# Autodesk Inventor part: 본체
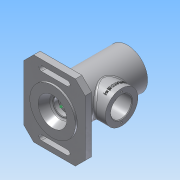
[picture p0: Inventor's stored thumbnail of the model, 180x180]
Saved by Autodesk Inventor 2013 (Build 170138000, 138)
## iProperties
Created: 2017-10
Part Number: 본체
Material: 알루미늄 6061
Document SubType Name: Modeling
Designer: Administrator
Density: 2.71 g/cm^3
Mass: 840.307 g
Surface Area: 700.57 cm^2
Volume: 310.076 cm^3
Author: Administrator
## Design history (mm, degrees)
sketch "스케치1"
  geometry: C1 r 31 at (0, 0); 1 further point
  constraints: 1 centre point, 1 coincident
  dimensions: "d0" = 62 diameter of C1
extrude "돌출1" new body sketch "스케치1" distance "d1" = 102; taper "d2" = 0 deg
node "작업 평면1"
sketch "스케치2"
  geometry: L1 (102, -31)-(102, 31) reference; C1 r 25 at (46, 0); 1 further point
  constraints: 1 centre point, 1 horizontal alignment
  dimensions: "d4" = 50 diameter of C1; "d5" = 56 distance from line of L1 C1.centre
extrude "돌출2" join sketch "스케치2" stored distance "d6" = 102; taper "d7" = 0 deg
sketch "스케치4"
  geometry: L1 (47, 58)-(-47, 58); L2 (-47, 58)-(-47, -58); L3 (-47, -58)-(47, -58); L4 (47, -58)-(47, 58); C1 r 31 at (0, 0) reference; 1 further point
  constraints: 8 end point, 2 parallel, 1 horizontal, 1 horizontal alignment, 1 midpoint, 1 perpendicular
  dimensions: "d10" = 116 distance of L1.end L2.end; "d12" = 47 distance of point (-47, 0) C1.centre; "d13" = 94 distance of L1.start L1.end
extrude "돌출3" join sketch "스케치4" distance "d14" = 10; taper "d15" = 0 deg
sketch "스케치5"
  geometry: C1 r 35 at (0, 0); 1 further point
  constraints: 1 centre point, 1 coincident
  dimensions: "d16" = 70 diameter of C1
extrude "돌출4" join sketch "스케치5" distance "d18" = 3; taper "d19" = 0 deg
hole "구멍1" diameter "d22" = 40.376; stored, may be unused: countersink angle "d26" = 90 deg, drill point angle "d28" = 0 deg; dims "d20" = 10, "d21" = 10, "d23" = 6, "d24" = 4, "d25" = 2, "d27" = 9
sketch "스케치6"
  geometry: C1 r 20.188 at (0, 0) reference; 1 further point
  constraints: 1 coincident
hole "구멍2" sketch "스케치6" at (0, 0) diameter "d29" = 40; stored, may be unused: countersink angle "d33" = 90 deg, drill point angle "d35" = 0 deg; dims "d30" = 6, "d31" = 48, "d32" = 3, "d34" = 12
sketch "스케치7"
  geometry: C1 r 20 at (0, 0) reference; C2 r 17.5 at (0, 0)
  constraints: 1 centre point, 1 coincident
  dimensions: "d36" = 35 diameter of C2
extrude "돌출5" cut sketch "스케치7" distance "d37" = 3.25; taper "d38" = 0 deg
sketch "스케치8"
  geometry: C1 r 17.5 at (0, 0) reference; 1 further point
  constraints: 1 coincident
hole "구멍3" sketch "스케치8" at (0, 0) diameter "d39" = 35; stored, may be unused: countersink angle "d43" = 90 deg, drill point angle "d45" = 0 deg; dims "d40" = 6, "d41" = 37, "d42" = 1.75, "d44" = 12.75
sketch "스케치9"
  geometry: C1 r 17.5 at (0, 0) reference; 1 further point
  constraints: 1 coincident
hole "구멍4" sketch "스케치9" at (0, 0) diameter "d46" = 35; stored, may be unused: countersink angle "d50" = 90 deg, drill point angle "d52" = 0 deg; dims "d47" = 6, "d48" = 52, "d49" = 38, "d51" = 49
sketch "스케치11"
  geometry: C1 r 17.5 at (0, 0) reference; 1 further point
  constraints: 1 coincident
hole "구멍5" sketch "스케치11" at (0, 0) diameter "d53" = 20; stored, may be unused: countersink angle "d57" = 90 deg, drill point angle "d59" = 0 deg; dims "d54" = 6, "d55" = 33, "d56" = 5, "d58" = 15
sketch "스케치14"
  geometry: L1 (-13, 35)-(-13, -35) reference; L2 (-13, 0)-(-13, 22); L3 (-13, 22)-(1, 16); L4 (1, 16)-(1, 0); L5 (1, 0)-(-13, 0)
  constraints: 8 end point, 1 midpoint, 1 parallel, 1 perpendicular, 1 point on line
  dimensions: "d70" = 22 distance of L2.start L2.end; "d71" = 16 distance of L3.end L4.end; "d72" = 14 distance of L4.end L2.start
revolve "회전1" sketch "스케치14" stored, may be unused: angle "d73" = 90 deg
sketch "스케치16"
  geometry: L1 (1, 16)-(1, -16) reference; L2 (1, 0)-(1, 12.5); L3 (1, 12.5)-(8.3, 12.5); L4 (8.3, 12.5)-(8.3, 10); L5 (8.3, 10)-(11, 10); L6 (11, 10)-(11, 0); L7 (11, 0)-(1, 0); 1 further point
  constraints: 12 end point, 3 perpendicular, 2 parallel, 1 midpoint, 1 point on line
  dimensions: "d74" = 12.5 distance of L2.start L2.end; "d75" = 7.3 distance of L2.end L3.end; "d76" = 10 distance of L5.end L6.end; "d77" = 2.7 distance of L4.end L5.end
revolve "회전2" sketch "스케치16" stored, may be unused: angle "d78" = 90 deg
sketch "스케치17"
  geometry: 1 further point
sketch "스케치18"
  geometry: 1 further point
sketch "스케치19"
  geometry: L1 (-47, -58)-(-47, 58) reference; L2 (20, 50)-(-20, 50); L3 (20, 42)-(-20, 42); C1 r 31 at (0, 0) reference; A1 r 4 centre (20, 46) between (20, 42) and (20, 50); A2 r 4 centre (-20, 46) between (-20, 50) and (-20, 42)
  constraints: 4 end point, 4 point on circle, 2 centre point, 2 parallel, 2 tangent, 1 equal radius, 1 perpendicular
  dimensions: "d79" = 40 distance of A2.centre A1.centre; "d81" = 4 radius of A1; "d82" = 46 vertical distance of C1.centre A2.centre; "d83" = 20 horizontal distance of C1.centre A2.centre
extrude "돌출6" cut sketch "스케치19" stored distance "d84" = 14; taper "d85" = 0 deg
sketch "스케치21"
  geometry: C1 r 25 at (0, 0) reference; A1 r 20.5 centre (0, 0) between (20.5, 0) and (-20.5, 0); 1 further point
  constraints: 2 horizontal alignment, 2 point on circle, 1 centre point, 1 coincident
  dimensions: "d86" = 41 diameter of A1
hole "구멍6" sketch "스케치21" at (20.5, 0), (-20.5, 0) diameter "d87" = 2.459; stored, may be unused: countersink angle "d91" = 90 deg, drill point angle "d93" = 118 deg; dims "d88" = 6, "d89" = 44, "d90" = 5, "d92" = 8
hole "구멍7" diameter "d96" = 32; stored, may be unused: countersink angle "d100" = 90 deg, drill point angle "d102" = 0 deg; dims "d94" = 10, "d95" = 10, "d97" = 6, "d98" = 44, "d99" = 5, "d101" = 40
chamfer "모따기1" distance "d104" = 1; stored, may be unused: second distance "d105" = 2, angle "d106" = 45 deg
chamfer "모따기2" distance "d107" = 1; stored, may be unused: second distance "d108" = 2, angle "d109" = 30 deg
chamfer "모따기3" distance "d110" = 1; stored, may be unused: second distance "d111" = 2, angle "d112" = 30 deg
fillet "모깎기2" dims "d113" = 3
chamfer "모따기4" distance "d114" = 1; stored, may be unused: second distance "d115" = 2, angle "d116" = 30 deg
node "작업 평면2"
sketch "스케치23"
  geometry: L1 (47, 71)-(47, 21) reference; L2 (31, 102)-(-31, 102) reference; 2 further points
  constraints: 1 other
  dimensions: "d118" = 10 distance from line of L1 point (37, 46); "d119" = 56 distance from line of L2 point (37, 46)
feature "엠보싱1" sketch "스케치23" dims "d0" = 62, "d120" = 0.5, "d121" = 0
chamfer "모따기5" distance "d122" = 15; stored, may be unused: second distance "d123" = 2, angle "d124" = 30 deg
chamfer "모따기6" distance "d125" = 1; stored, may be unused: second distance "d126" = 2, angle "d127" = 30 deg
fillet "모깎기3" dims "d128" = 0.3
fillet "모깎기4" dims "d129" = 3
fillet "모깎기5" dims "d130" = 3
node "솔리드1"
mirror "대칭1"
other parameters: "d3" = 47, "d117" = 148
